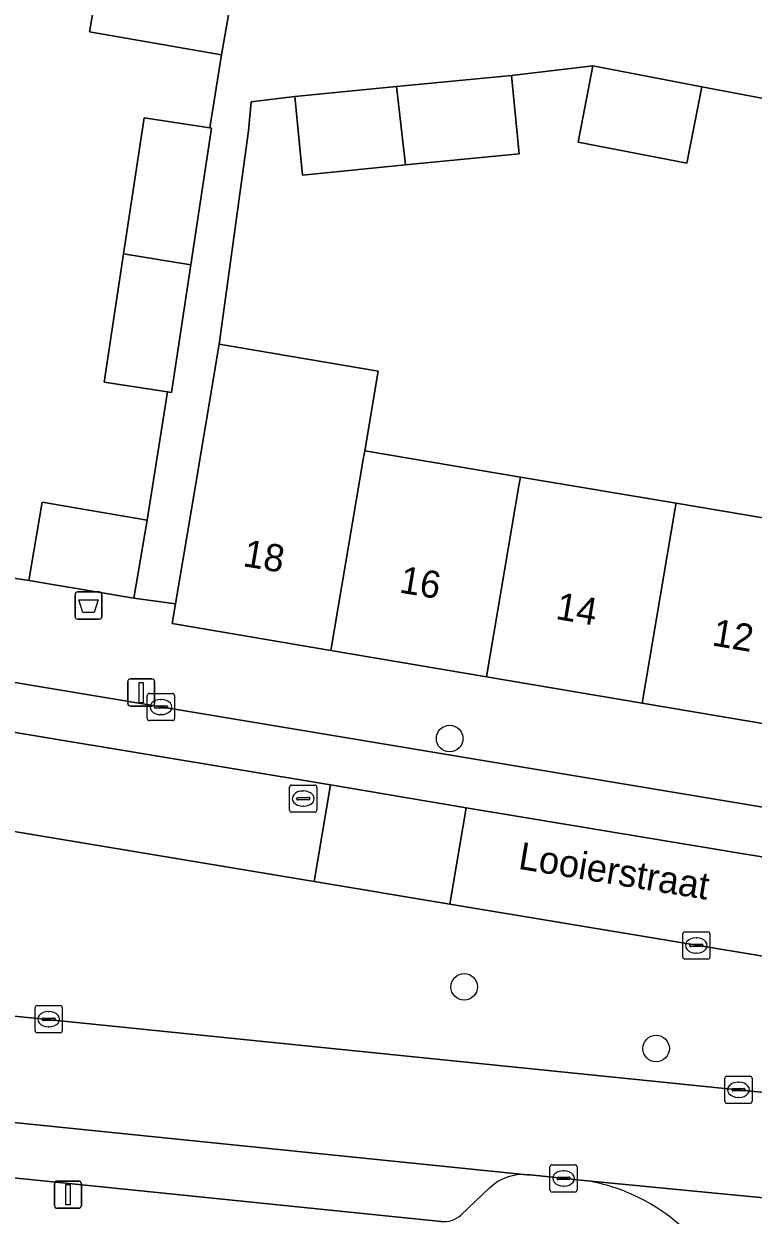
# Model space of a CAD drawing. Extents: x 160856 to 161310, y 384024 to 384878.
# Drawn here: x 161167.28 to 161194.13, y 384674.64 to 384718.5 of the extents above; entities that cross this region are included whole.
import ezdxf

# ---------------------------------------------------------------- set-up
doc = ezdxf.new("R2010")
doc.units = 0
for name, color, linetype in [('IMGEO_Afvalbak', 7, 'Continuous'), ('IMGEO_Boom', 7, 'Continuous'), ('IMGEO_Erf', 7, 'Continuous'), ('IMGEO_Groenvoorziening', 7, 'Continuous'), ('IMGEO_Kolk', 7, 'Continuous'), ('IMGEO_Lichtmast', 7, 'Continuous'), ('IMGEO_Muur', 7, 'Continuous'), ('IMGEO_Openbare_ruimte_label', 7, 'Continuous'), ('IMGEO_Pand', 7, 'Continuous'), ('IMGEO_Pand_nummerreeks', 7, 'Continuous'), ('IMGEO_Parkeervlak_open', 7, 'Continuous'), ('IMGEO_Rijbaan_lokaal_open', 7, 'Continuous'), ('IMGEO_Rioolput', 7, 'Continuous'), ('IMGEO_Voetpad_open', 7, 'Continuous')]:
    doc.layers.add(name, color=color, linetype=linetype)

msp = doc.modelspace()

# ---------------------------------------------------------------- linework, layer by layer
at = {"layer": 'IMGEO_Afvalbak'}
for p, q in [((161169.166, 384696.687), (161169.166, 384697.487)), ((161169.166, 384697.487), (161169.166, 384696.687)), ((161169.266, 384697.587), (161170.056, 384697.587)), ((161170.056, 384697.587), (161169.266, 384697.587)), ((161170.156, 384697.487), (161170.156, 384696.687)), ((161170.156, 384696.687), (161170.156, 384697.487)), ((161170.056, 384696.587), (161169.266, 384696.587)), ((161169.266, 384696.587), (161170.056, 384696.587))]:
    msp.add_line(p, q, dxfattribs=at)
msp.add_lwpolyline([(161169.309, 384697.301), (161170.013, 384697.301), (161169.864, 384696.831), (161169.458, 384696.831), (161169.309, 384697.301)], dxfattribs=at)
for centre, start, end in [((161169.266, 384697.487), 90, 180), ((161169.266, 384697.487), 90, 180), ((161170.056, 384697.487), 0, 90), ((161170.056, 384697.487), 360, 90), ((161169.266, 384696.687), 180, 270), ((161169.266, 384696.687), 180, 270), ((161170.056, 384696.687), 270, 0), ((161170.056, 384696.687), 270, 0)]:
    msp.add_arc(centre, 0.1, start, end, dxfattribs=at)
at = {"layer": 'IMGEO_Boom'}
for centre in [(161182.958, 384692.189), (161183.493, 384683.049), (161190.558, 384680.779)]:
    msp.add_circle(centre, 0.489, dxfattribs=at)
at = {"layer": 'IMGEO_Erf'}
for points in [[(161161.046, 384724.302), (161160.032, 384718.155), (161159.018, 384712.008), (161158.007, 384705.881), (161154.738, 384706.42), (161153.7, 384700.13), (161167.463, 384698.012), (161167.949, 384700.888), (161171.82, 384700.234), (161172.574, 384704.956), (161170.234, 384705.31), (161170.95, 384710.04), (161171.706, 384715.038), (161174.126, 384714.672), (161174.555, 384717.356), (161169.694, 384718.211), (161170.511, 384722.85)], [(161195.881, 384715.501), (161192.238, 384716.183), (161191.691, 384713.369), (161187.686, 384714.146), (161188.233, 384716.961), (161185.235, 384716.603), (161185.517, 384713.714), (161181.333, 384713.306), (161177.545, 384712.936), (161177.263, 384715.825), (161175.651, 384715.631), (161175.548, 384714.563), (161174.476, 384706.71), (161180.326, 384705.721), (161179.83, 384702.787), (161185.562, 384701.818), (161191.294, 384700.85), (161197.026, 384699.881)]]:
    msp.add_lwpolyline(points, dxfattribs=at)
at = {"layer": 'IMGEO_Groenvoorziening'}
for points in [[(161195.22, 384684.061), (161182.965, 384686.099), (161177.965, 384686.926), (161163.306, 384689.368), (161162.797, 384686.255), (161158.825, 384686.907), (161159.285, 384690.038), (161144.834, 384692.446), (161144.71, 384692.468)], [(161143.107, 384684.751), (161143.417, 384684.619), (161144.055, 384684.484), (161147.028, 384683.998), (161194.415, 384679.172), (161194.533, 384679.161)]]:
    msp.add_lwpolyline(points, dxfattribs=at)
at = {"layer": 'IMGEO_Kolk'}
for p, q in [((161171.826, 384692.925), (161171.826, 384693.777)), ((161171.901, 384693.851), (161172.753, 384693.851)), ((161172.314, 384693.631), (161172.339, 384693.631)), ((161172.827, 384693.777), (161172.827, 384692.925)), ((161172.085, 384693.345), (161172.085, 384693.357)), ((161172.523, 384693.308), (161172.125, 384693.308)), ((161172.128, 384693.394), (161172.526, 384693.394)), ((161172.337, 384693.071), (161172.312, 384693.071)), ((161172.569, 384693.357), (161172.569, 384693.345)), ((161172.753, 384692.851), (161171.901, 384692.851)), ((161191.54, 384684.147), (161191.54, 384684.999)), ((161191.615, 384685.073), (161192.467, 384685.073)), ((161192.028, 384684.853), (161192.053, 384684.853)), ((161192.541, 384684.999), (161192.541, 384684.147)), ((161191.799, 384684.567), (161191.799, 384684.579)), ((161192.237, 384684.53), (161191.839, 384684.53)), ((161191.842, 384684.616), (161192.24, 384684.616)), ((161192.051, 384684.293), (161192.026, 384684.293)), ((161192.283, 384684.579), (161192.283, 384684.567)), ((161192.467, 384684.073), (161191.615, 384684.073)), ((161167.694, 384681.432), (161167.694, 384682.284)), ((161167.769, 384682.358), (161168.621, 384682.358)), ((161168.182, 384682.138), (161168.207, 384682.138)), ((161168.695, 384682.284), (161168.695, 384681.432)), ((161167.953, 384681.852), (161167.953, 384681.864)), ((161168.391, 384681.815), (161167.993, 384681.815)), ((161167.996, 384681.901), (161168.394, 384681.901)), ((161168.437, 384681.864), (161168.437, 384681.852)), ((161168.621, 384681.358), (161167.769, 384681.358)), ((161168.205, 384681.578), (161168.18, 384681.578)), ((161193.091, 384678.835), (161193.091, 384679.687)), ((161193.166, 384679.761), (161194.018, 384679.761)), ((161193.579, 384679.541), (161193.604, 384679.541)), ((161194.092, 384679.687), (161194.092, 384678.835)), ((161193.35, 384679.255), (161193.35, 384679.267)), ((161193.788, 384679.218), (161193.39, 384679.218)), ((161193.393, 384679.304), (161193.791, 384679.304)), ((161193.602, 384678.981), (161193.577, 384678.981)), ((161193.834, 384679.267), (161193.834, 384679.255)), ((161194.018, 384678.761), (161193.166, 384678.761)), ((161186.651, 384675.571), (161186.651, 384676.423)), ((161186.726, 384676.497), (161187.578, 384676.497)), ((161187.652, 384676.423), (161187.652, 384675.571)), ((161186.91, 384675.991), (161186.91, 384676.003)), ((161187.348, 384675.954), (161186.95, 384675.954)), ((161186.953, 384676.04), (161187.351, 384676.04)), ((161187.139, 384676.277), (161187.164, 384676.277)), ((161187.394, 384676.003), (161187.394, 384675.991)), ((161187.578, 384675.497), (161186.726, 384675.497)), ((161187.162, 384675.717), (161187.137, 384675.717))]:
    msp.add_line(p, q, dxfattribs=at)
for points in [[(161171.826, 384692.925), (161171.826, 384693.777)], [(161171.901, 384693.851), (161172.753, 384693.851)], [(161172.827, 384693.777), (161172.827, 384692.925)], [(161172.753, 384692.851), (161171.901, 384692.851)], [(161191.54, 384684.147), (161191.54, 384684.999)], [(161191.615, 384685.073), (161192.467, 384685.073)], [(161192.541, 384684.999), (161192.541, 384684.147)], [(161192.467, 384684.073), (161191.615, 384684.073)], [(161167.694, 384681.432), (161167.694, 384682.284)], [(161167.769, 384682.358), (161168.621, 384682.358)], [(161168.695, 384682.284), (161168.695, 384681.432)], [(161168.621, 384681.358), (161167.769, 384681.358)], [(161193.091, 384678.835), (161193.091, 384679.687)], [(161193.166, 384679.761), (161194.018, 384679.761)], [(161194.092, 384679.687), (161194.092, 384678.835)], [(161194.018, 384678.761), (161193.166, 384678.761)], [(161186.651, 384675.571), (161186.651, 384676.423)], [(161186.726, 384676.497), (161187.578, 384676.497)], [(161187.652, 384676.423), (161187.652, 384675.571)], [(161187.578, 384675.497), (161186.726, 384675.497)]]:
    msp.add_lwpolyline(points, dxfattribs=at)
for centre, radius, start, end in [((161171.903, 384693.775), 0.0765, 91.552, 178.448), ((161171.903, 384693.775), 0.0765, 91.552, 178.448), ((161172.751, 384693.775), 0.0765, 1.552, 88.448), ((161172.751, 384693.775), 0.0765, 1.552, 88.448), ((161172.125, 384693.354), 0.0403, 85.8775, 175.7526), ((161172.122, 384693.344), 0.0366, 178.938, 274.7102), ((161172.526, 384693.351), 0.043, 264.8664, 352.4533), ((161172.53, 384693.356), 0.0386, 1.7309, 96.639), ((161171.903, 384692.927), 0.0765, 181.552, 268.448), ((161171.903, 384692.927), 0.0765, 181.552, 268.448), ((161172.751, 384692.927), 0.0765, 271.552, 358.448), ((161172.751, 384692.927), 0.0765, 271.552, 358.448), ((161191.617, 384684.997), 0.0765, 91.552, 178.448), ((161191.617, 384684.997), 0.0765, 91.552, 178.448), ((161192.465, 384684.997), 0.0765, 1.552, 88.448), ((161192.465, 384684.997), 0.0765, 1.552, 88.448), ((161191.839, 384684.576), 0.0403, 85.8775, 175.7526), ((161191.836, 384684.566), 0.0366, 178.938, 274.7102), ((161192.24, 384684.573), 0.043, 264.8664, 352.4533), ((161192.244, 384684.578), 0.0386, 1.7309, 96.639), ((161191.617, 384684.149), 0.0765, 181.552, 268.448), ((161191.617, 384684.149), 0.0765, 181.552, 268.448), ((161192.465, 384684.149), 0.0765, 271.552, 358.448), ((161192.465, 384684.149), 0.0765, 271.552, 358.448), ((161167.771, 384682.282), 0.0765, 91.552, 178.448), ((161167.771, 384682.282), 0.0765, 91.552, 178.448), ((161168.619, 384682.282), 0.0765, 1.552, 88.448), ((161168.619, 384682.282), 0.0765, 1.552, 88.448), ((161167.993, 384681.861), 0.0403, 85.8775, 175.7526), ((161167.99, 384681.851), 0.0366, 178.938, 274.7102), ((161168.394, 384681.858), 0.043, 264.8664, 352.4533), ((161168.398, 384681.863), 0.0386, 1.7309, 96.639), ((161167.771, 384681.434), 0.0765, 181.552, 268.448), ((161167.771, 384681.434), 0.0765, 181.552, 268.448), ((161168.619, 384681.434), 0.0765, 271.552, 358.448), ((161168.619, 384681.434), 0.0765, 271.552, 358.448), ((161193.168, 384679.685), 0.0765, 91.552, 178.448), ((161193.168, 384679.685), 0.0765, 91.552, 178.448), ((161194.016, 384679.685), 0.0765, 1.552, 88.448), ((161194.016, 384679.685), 0.0765, 1.552, 88.448), ((161193.39, 384679.264), 0.0403, 85.8775, 175.7526), ((161193.387, 384679.254), 0.0366, 178.938, 274.7102), ((161193.791, 384679.261), 0.043, 264.8664, 352.4533), ((161193.795, 384679.266), 0.0386, 1.7309, 96.639), ((161193.168, 384678.837), 0.0765, 181.552, 268.448), ((161193.168, 384678.837), 0.0765, 181.552, 268.448), ((161194.016, 384678.837), 0.0765, 271.552, 358.448), ((161194.016, 384678.837), 0.0765, 271.552, 358.448), ((161186.728, 384676.421), 0.0765, 91.552, 178.448), ((161186.728, 384676.421), 0.0765, 91.552, 178.448), ((161187.576, 384676.421), 0.0765, 1.552, 88.448), ((161187.576, 384676.421), 0.0765, 1.552, 88.448), ((161186.95, 384676), 0.0403, 85.8775, 175.7526), ((161186.947, 384675.99), 0.0366, 178.938, 274.7102), ((161187.351, 384675.997), 0.043, 264.8664, 352.4533), ((161187.355, 384676.002), 0.0386, 1.7309, 96.639), ((161186.728, 384675.573), 0.0765, 181.552, 268.448), ((161186.728, 384675.573), 0.0765, 181.552, 268.448), ((161187.576, 384675.573), 0.0765, 271.552, 358.448), ((161187.576, 384675.573), 0.0765, 271.552, 358.448)]:
    msp.add_arc(centre, radius, start, end, dxfattribs=at)
for centre, major_axis, ratio, start_param, end_param in [((161172.313, 384693.351), (-0.387, 0.002), 0.722429, 4.712389, 7.853982), ((161172.338, 384693.351), (-0.39, 0.002), 0.717154, 1.570796, 4.712389), ((161192.027, 384684.573), (-0.387, 0.002), 0.722429, 4.712389, 7.853982), ((161192.052, 384684.573), (-0.39, 0.002), 0.717154, 1.570796, 4.712389), ((161168.181, 384681.858), (-0.387, 0.002), 0.722429, 4.712389, 7.853982), ((161168.206, 384681.858), (-0.39, 0.002), 0.717154, 1.570796, 4.712389), ((161193.578, 384679.261), (-0.387, 0.002), 0.722429, 4.712389, 7.853982), ((161193.603, 384679.261), (-0.39, 0.002), 0.717154, 1.570796, 4.712389), ((161187.138, 384675.997), (-0.387, 0.002), 0.722429, 4.712389, 7.853982), ((161187.163, 384675.997), (-0.39, 0.002), 0.717154, 1.570796, 4.712389)]:
    msp.add_ellipse(centre, major_axis=major_axis, ratio=ratio, start_param=start_param, end_param=end_param, dxfattribs=at)
at = {"layer": 'IMGEO_Lichtmast'}
for p, q in [((161171.206, 384694.383), (161171.996, 384694.383)), ((161171.996, 384694.383), (161171.206, 384694.383)), ((161171.106, 384693.483), (161171.106, 384694.283)), ((161171.106, 384694.283), (161171.106, 384693.483)), ((161172.096, 384694.283), (161172.096, 384693.483)), ((161172.096, 384693.483), (161172.096, 384694.283)), ((161171.996, 384693.383), (161171.206, 384693.383)), ((161171.206, 384693.383), (161171.996, 384693.383)), ((161168.51, 384675.9), (161169.3, 384675.9)), ((161169.3, 384675.9), (161168.51, 384675.9)), ((161168.41, 384675), (161168.41, 384675.8)), ((161168.41, 384675.8), (161168.41, 384675)), ((161169.4, 384675.8), (161169.4, 384675)), ((161169.4, 384675), (161169.4, 384675.8)), ((161169.3, 384674.9), (161168.51, 384674.9)), ((161168.51, 384674.9), (161169.3, 384674.9))]:
    msp.add_line(p, q, dxfattribs=at)
for points in [[(161171.526, 384694.258), (161171.676, 384694.258), (161171.676, 384693.508), (161171.526, 384693.508), (161171.526, 384694.258)], [(161168.83, 384675.775), (161168.98, 384675.775), (161168.98, 384675.025), (161168.83, 384675.025), (161168.83, 384675.775)]]:
    msp.add_lwpolyline(points, dxfattribs=at)
for centre, start, end in [((161171.206, 384694.283), 90, 180), ((161171.206, 384694.283), 90, 180), ((161171.996, 384694.283), 0, 90), ((161171.996, 384694.283), 360, 90), ((161171.206, 384693.483), 180, 270), ((161171.206, 384693.483), 180, 270), ((161171.996, 384693.483), 270, 0), ((161171.996, 384693.483), 270, 0), ((161168.51, 384675.8), 90, 180), ((161168.51, 384675.8), 90, 180), ((161169.3, 384675.8), 0, 90), ((161169.3, 384675.8), 360, 90), ((161168.51, 384675), 180, 270), ((161168.51, 384675), 180, 270), ((161169.3, 384675), 270, 0), ((161169.3, 384675), 270, 0)]:
    msp.add_arc(centre, 0.1, start, end, dxfattribs=at)
at = {"layer": 'IMGEO_Muur'}
msp.add_lwpolyline([(161153.7, 384700.13), (161167.463, 384698.012)], dxfattribs=at)
at = {"layer": 'IMGEO_Pand'}
for points in [[(161175.372, 384721.995), (161170.511, 384722.85), (161169.694, 384718.211), (161174.555, 384717.356)], [(161192.238, 384716.183), (161188.233, 384716.961), (161187.686, 384714.146), (161191.691, 384713.369)], [(161181.333, 384713.306), (161185.517, 384713.714), (161185.235, 384716.603), (161180.997, 384716.19)], [(161181.333, 384713.306), (161180.997, 384716.19), (161177.263, 384715.825), (161177.545, 384712.936)], [(161174.126, 384714.672), (161171.706, 384715.038), (161170.95, 384710.04), (161173.423, 384709.631), (161174.184, 384714.663)], [(161173.423, 384709.631), (161170.95, 384710.04), (161170.234, 384705.31), (161172.574, 384704.956), (161172.712, 384704.935)], [(161178.587, 384695.434), (161179.787, 384702.533), (161179.83, 384702.787), (161180.326, 384705.721), (161174.476, 384706.71), (161173.98, 384703.776), (161173.571, 384701.354), (161172.859, 384697.147), (161172.737, 384696.423)], [(161185.562, 384701.818), (161179.83, 384702.787), (161179.787, 384702.533), (161178.587, 384695.434), (161184.319, 384694.465), (161185.519, 384701.564)], [(161190.051, 384693.497), (161191.251, 384700.595), (161191.294, 384700.85), (161185.562, 384701.818), (161185.519, 384701.564), (161184.319, 384694.465)], [(161167.463, 384698.012), (161171.334, 384697.358), (161171.82, 384700.234), (161167.949, 384700.888)], [(161195.783, 384692.528), (161196.983, 384699.626), (161197.026, 384699.881), (161191.294, 384700.85), (161191.251, 384700.595), (161190.051, 384693.497)]]:
    msp.add_lwpolyline(points, close=True, dxfattribs=at)
at = {"layer": 'IMGEO_Parkeervlak_open'}
for points in [[(161143.528, 384696.307), (161178.569, 384690.489), (161183.564, 384689.645), (161225.466, 384682.697), (161225.789, 384684.447), (161146.911, 384697.588)], [(161185.816, 384676.135), (161143.188, 384680.479)], [(161146.327, 384678.119), (161182.64, 384674.41)], [(161183.374, 384674.644), (161184.431, 384675.657)]]:
    msp.add_lwpolyline(points, dxfattribs=at)
for centre, radius, start, end in [((161185.674, 384674.302), 1.838, 85.557, 132.5248), ((161182.724, 384675.414), 1.008, 265.2063, 310.1584)]:
    msp.add_arc(centre, radius, start, end, dxfattribs=at)
at = {"layer": 'IMGEO_Rijbaan_lokaal_open'}
for points in [[(161135.047, 384698.382), (161134.131, 384691.822), (161135.496, 384692.326), (161139.724, 384693.284), (161140.109, 384693.275), (161144.71, 384692.468), (161144.834, 384692.446), (161159.285, 384690.038), (161163.306, 384689.368), (161177.965, 384686.926), (161178.569, 384690.489)], [(161178.569, 384690.489), (161143.528, 384696.307), (161143.363, 384696.334), (161137.98, 384697.23)], [(161197.076, 384678.923), (161194.533, 384679.161), (161194.415, 384679.172), (161147.028, 384683.998), (161144.055, 384684.484), (161143.417, 384684.619), (161143.107, 384684.751), (161139.04, 384686.479), (161138.533, 384686.696), (161133.972, 384690.601), (161133.242, 384681.338)], [(161225.466, 384682.697), (161183.564, 384689.645), (161182.965, 384686.099), (161195.22, 384684.061), (161197.732, 384683.627), (161223.711, 384679.283)], [(161135.61, 384681.376), (161139.001, 384680.825), (161143.066, 384680.491), (161143.188, 384680.479), (161185.816, 384676.135), (161185.922, 384676.125), (161187.912, 384675.92), (161202.637, 384674.492), (161251.411, 384669.458), (161251.394, 384669.225), (161252.77, 384669.111), (161253.501, 384675.224), (161252.277, 384675.194), (161251.143, 384675.297), (161239.508, 384676.544), (161229.088, 384676.847)], [(161202.637, 384674.492), (161187.912, 384675.92)]]:
    msp.add_lwpolyline(points, dxfattribs=at)
msp.add_lwpolyline([(161183.564, 384689.645), (161178.569, 384690.489), (161177.965, 384686.926), (161182.965, 384686.099)], close=True, dxfattribs=at)
for centre, radius, start, end in [((161186.92, 384669.199), 6.794, 65.3357, 81.6027), ((161186.918, 384669.185), 6.807, 35.0767, 65.3699)]:
    msp.add_arc(centre, radius, start, end, dxfattribs=at)
at = {"layer": 'IMGEO_Rioolput'}
for p, q in [((161177.065, 384689.554), (161177.065, 384690.406)), ((161177.14, 384690.48), (161177.992, 384690.48)), ((161178.066, 384690.406), (161178.066, 384689.554)), ((161177.324, 384689.974), (161177.324, 384689.986)), ((161177.762, 384689.937), (161177.364, 384689.937)), ((161177.367, 384690.023), (161177.765, 384690.023)), ((161177.553, 384690.26), (161177.578, 384690.26)), ((161177.808, 384689.986), (161177.808, 384689.974)), ((161177.576, 384689.7), (161177.551, 384689.7)), ((161177.992, 384689.48), (161177.14, 384689.48))]:
    msp.add_line(p, q, dxfattribs=at)
for points in [[(161177.065, 384689.554), (161177.065, 384690.406)], [(161177.14, 384690.48), (161177.992, 384690.48)], [(161178.066, 384690.406), (161178.066, 384689.554)], [(161177.992, 384689.48), (161177.14, 384689.48)]]:
    msp.add_lwpolyline(points, dxfattribs=at)
for centre, radius, start, end in [((161177.142, 384690.404), 0.0765, 91.552, 178.448), ((161177.142, 384690.404), 0.0765, 91.552, 178.448), ((161177.99, 384690.404), 0.0765, 1.552, 88.448), ((161177.99, 384690.404), 0.0765, 1.552, 88.448), ((161177.364, 384689.983), 0.0403, 85.8775, 175.7526), ((161177.361, 384689.973), 0.0366, 178.938, 274.7102), ((161177.765, 384689.98), 0.043, 264.8664, 352.4533), ((161177.769, 384689.985), 0.0386, 1.7309, 96.639), ((161177.142, 384689.556), 0.0765, 181.552, 268.448), ((161177.142, 384689.556), 0.0765, 181.552, 268.448), ((161177.99, 384689.556), 0.0765, 271.552, 358.448), ((161177.99, 384689.556), 0.0765, 271.552, 358.448)]:
    msp.add_arc(centre, radius, start, end, dxfattribs=at)
for centre, major_axis, ratio, start_param, end_param in [((161177.552, 384689.98), (-0.387, 0.002), 0.722429, 4.712389, 7.853982), ((161177.577, 384689.98), (-0.39, 0.002), 0.717154, 1.570796, 4.712389)]:
    msp.add_ellipse(centre, major_axis=major_axis, ratio=ratio, start_param=start_param, end_param=end_param, dxfattribs=at)
at = {"layer": 'IMGEO_Voetpad_open'}
for points in [[(161175.372, 384721.995), (161174.555, 384717.356), (161174.126, 384714.672), (161174.184, 384714.663), (161173.423, 384709.631), (161172.712, 384704.935), (161172.574, 384704.956), (161171.82, 384700.234), (161171.334, 384697.358), (161172.859, 384697.147), (161173.571, 384701.354), (161173.98, 384703.776), (161174.476, 384706.71), (161175.548, 384714.563), (161175.651, 384715.631), (161177.263, 384715.825), (161180.997, 384716.19), (161185.235, 384716.603), (161188.233, 384716.961), (161192.238, 384716.183), (161195.881, 384715.501)], [(161172.737, 384696.423), (161172.859, 384697.147), (161171.334, 384697.358), (161167.463, 384698.012), (161153.7, 384700.13), (161146.719, 384701.281), (161145.313, 384701.438), (161144.584, 384696.476)], [(161146.911, 384697.588), (161225.789, 384684.447), (161230.353, 384683.679)], [(161254.432, 384675.336), (161255.607, 384680.798), (161253.034, 384681.113), (161241.061, 384682.538), (161238.896, 384682.765), (161230.514, 384686.747), (161226.561, 384687.415), (161224.56, 384687.664), (161218.712, 384688.652), (161212.98, 384689.621), (161207.248, 384690.59), (161201.516, 384691.559), (161195.783, 384692.528), (161190.051, 384693.497), (161184.319, 384694.465), (161178.587, 384695.434), (161172.737, 384696.423)], [(161182.64, 384674.41), (161146.327, 384678.119)], [(161187.912, 384675.92), (161185.922, 384676.125), (161185.816, 384676.135)], [(161184.431, 384675.657), (161183.374, 384674.644)]]:
    msp.add_lwpolyline(points, dxfattribs=at)
for centre, radius, start, end in [((161185.674, 384674.302), 1.838, 85.557, 132.5248), ((161186.92, 384669.199), 6.794, 65.3357, 81.6027), ((161186.918, 384669.185), 6.807, 35.0767, 65.3699), ((161182.724, 384675.414), 1.008, 265.2063, 310.1584)]:
    msp.add_arc(centre, radius, start, end, dxfattribs=at)

# ---------------------------------------------------------------- texts
at = {"layer": 'IMGEO_Openbare_ruimte_label'}
msp.add_text('Looierstraat', height=1, rotation=350.6789, dxfattribs=at).set_placement((161185.452, 384687.399))
at = {"layer": 'IMGEO_Pand_nummerreeks'}
for s, p in [('18', (161175.313, 384698.543)), ('16', (161181.068, 384697.571)), ('14', (161186.827, 384696.597)), ('12', (161192.582, 384695.624))]:
    msp.add_text(s, height=1, rotation=350.4067, dxfattribs=at).set_placement(p)

doc.saveas('drawing.dxf')
